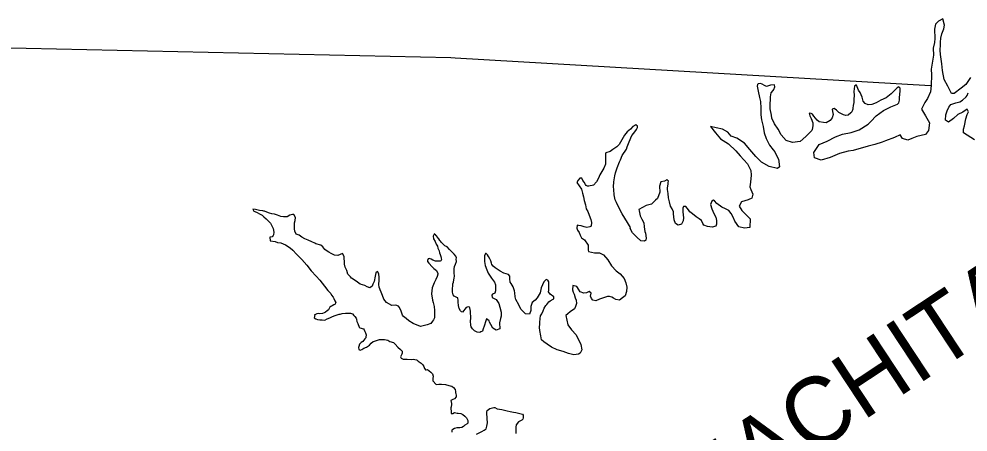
# Model space of a CAD drawing. Extents: x -492261 to -432772, y 1441225 to 1452922.
# Drawn here: x -461436.6 to -461306.2, y 1452192.9 to 1452249.6 of the extents above; entities that cross this region are included whole.
import ezdxf

# ---------------------------------------------------------------- set-up
doc = ezdxf.new("R2010")
doc.units = 0
doc.layers.add('Default', color=7, linetype='Continuous')

msp = doc.modelspace()

# ---------------------------------------------------------------- linework, layer by layer
at = {"layer": 'Default'}
for points in [[(-461305.85, 1452241.57), (-461306.51, 1452240.63), (-461307.13, 1452240.12), (-461308.1, 1452239.36), (-461308.45, 1452239.4), (-461308.96, 1452240.4), (-461309.45, 1452241.32), (-461309.72, 1452242.54), (-461309.8, 1452243.44), (-461309.97, 1452244.74), (-461310.01, 1452245.35), (-461309.99, 1452246.07), (-461309.97, 1452246.45), (-461309.95, 1452246.97), (-461309.78, 1452247.58), (-461309.54, 1452248.26), (-461309.42, 1452248.74), (-461309.66, 1452249.61), (-461310.23, 1452249.33), (-461310.65, 1452248.89), (-461310.82, 1452248.22), (-461310.75, 1452246.91), (-461310.82, 1452246.39), (-461310.99, 1452245.61), (-461310.92, 1452244.63), (-461311.18, 1452243.27), (-461311.25, 1452242.72), (-461311.21, 1452241.95), (-461311.27, 1452240.47), (-461311.33, 1452239.59), (-461311.75, 1452238.71), (-461312.14, 1452238.15), (-461312.58, 1452237.22), (-461312.04, 1452236.3), (-461311.48, 1452235.35), (-461311.64, 1452234.32), (-461312.03, 1452233.77), (-461313.21, 1452233.5), (-461313.93, 1452233.19), (-461314.45, 1452232.98), (-461315.18, 1452233.22), (-461315.51, 1452233.69), (-461316.29, 1452233.36), (-461317.51, 1452232.87), (-461317.98, 1452232.68), (-461318.98, 1452232.37)], [(-461443.96, 1452245.81), (-461377.23, 1452244.31), (-461376.65, 1452244.29), (-461311.37, 1452240.49)], [(-461334.72, 1452240.75), (-461335.02, 1452240.72), (-461335.12, 1452240.6), (-461335.17, 1452240.39), (-461335.03, 1452239.69), (-461334.82, 1452238.82), (-461334.69, 1452238.3), (-461334.65, 1452237.39), (-461334.66, 1452236.47), (-461334.58, 1452235.77), (-461334.32, 1452234.84), (-461334.21, 1452233.99), (-461333.94, 1452233.19), (-461333.46, 1452232.3), (-461332.97, 1452231.65), (-461332.74, 1452231.38), (-461332.51, 1452230.88), (-461332.25, 1452230.36), (-461332.09, 1452229.31), (-461332.36, 1452229.08), (-461333.49, 1452229.34), (-461334.55, 1452229.95), (-461335.36, 1452230.74), (-461336.18, 1452231.69), (-461336.92, 1452232.58), (-461337.95, 1452233.24), (-461338.71, 1452233.51), (-461339.19, 1452234.08), (-461339.9, 1452234.49), (-461340.8, 1452234.65), (-461341.56, 1452234.87), (-461340.87, 1452233.98), (-461340.21, 1452233.18), (-461339.09, 1452232.45), (-461338.11, 1452231.53), (-461337.5, 1452230.84), (-461336.48, 1452229.75), (-461336.04, 1452228.83), (-461335.96, 1452228.18), (-461336.09, 1452227.23), (-461336.16, 1452226.57), (-461336.01, 1452226.2), (-461335.77, 1452225.55), (-461335.89, 1452225), (-461336.41, 1452224.77), (-461337.31, 1452224.53), (-461337.63, 1452223.9), (-461337.27, 1452223.33), (-461336.13, 1452222.17), (-461336.16, 1452221.01), (-461336.91, 1452220.9), (-461337.69, 1452221.09), (-461338.23, 1452221.86), (-461338.44, 1452222.41), (-461338.72, 1452222.91), (-461339.05, 1452223.33), (-461339.53, 1452223.55), (-461340.01, 1452223.77), (-461340.69, 1452224.26), (-461341, 1452224.63), (-461341.15, 1452224.75), (-461341.37, 1452224.62), (-461341.57, 1452224.15), (-461341.38, 1452223.57), (-461341.12, 1452222.92), (-461340.82, 1452222.4), (-461340.73, 1452221.93), (-461340.73, 1452221.45), (-461340.82, 1452221.17), (-461341.32, 1452221.02), (-461341.98, 1452221.11), (-461342.48, 1452221.3), (-461342.63, 1452221.55), (-461342.81, 1452221.95), (-461343.14, 1452222.17), (-461343.55, 1452222.44), (-461344.05, 1452222.88), (-461344.41, 1452223.16), (-461344.61, 1452223.43), (-461344.97, 1452223.85), (-461345.29, 1452223.87), (-461345.39, 1452223.64), (-461345.36, 1452223.12), (-461345.3, 1452222.32), (-461345.32, 1452221.89), (-461345.56, 1452221.44), (-461345.99, 1452221.3), (-461346.37, 1452221.55), (-461346.57, 1452222.05), (-461346.66, 1452222.87), (-461346.66, 1452223.15), (-461346.82, 1452223.57), (-461347.07, 1452223.92), (-461347.21, 1452224.5), (-461347.34, 1452225.07), (-461347.4, 1452225.67), (-461347.48, 1452226.2), (-461347.46, 1452226.37), (-461347.39, 1452226.97), (-461347.39, 1452227.17), (-461347.34, 1452227.35)], [(-461318.98, 1452232.37), (-461319.9, 1452232.13), (-461321.95, 1452231.55), (-461322.67, 1452231.47), (-461323.85, 1452231.15), (-461325.12, 1452230.61), (-461326.36, 1452230.22), (-461327.27, 1452230.53), (-461327.36, 1452231.28), (-461326.64, 1452232.39), (-461325.55, 1452232.83), (-461324.4, 1452233.42), (-461323.43, 1452233.79), (-461322.23, 1452234.03), (-461321.16, 1452234.4), (-461319.89, 1452235.16), (-461319.55, 1452235.54), (-461318.8, 1452236.31), (-461317.81, 1452237.05), (-461316.82, 1452237.54), (-461315.89, 1452237.9), (-461315.7, 1452238.1), (-461315.63, 1452238.48), (-461315.63, 1452238.85), (-461315.52, 1452239.68), (-461315.5, 1452240.11), (-461315.7, 1452240.28), (-461315.95, 1452240.15), (-461316.25, 1452239.85), (-461316.74, 1452239.32), (-461317.46, 1452238.8), (-461318.16, 1452238.47), (-461318.8, 1452238.11), (-461319.4, 1452237.85), (-461319.9, 1452237.82), (-461320.33, 1452237.99), (-461320.58, 1452238.31), (-461320.72, 1452238.86), (-461321.03, 1452239.51), (-461321.26, 1452239.83), (-461321.52, 1452240.53), (-461321.59, 1452240.53), (-461321.79, 1452240.4), (-461321.88, 1452239.67), (-461321.85, 1452239.17), (-461321.87, 1452238.54), (-461321.86, 1452238.34), (-461321.88, 1452238.14), (-461321.95, 1452237.74), (-461322, 1452237.39), (-461322.02, 1452237.24), (-461322.17, 1452236.86), (-461322.29, 1452236.71), (-461322.66, 1452236.43), (-461322.96, 1452236.35), (-461323.32, 1452236.45), (-461323.92, 1452236.76), (-461324.25, 1452237.11), (-461324.6, 1452237.33), (-461324.85, 1452237.25), (-461324.82, 1452236.93), (-461324.72, 1452236.48), (-461324.86, 1452236.02), (-461325.13, 1452235.67), (-461325.66, 1452235.36), (-461326.06, 1452235.38), (-461326.63, 1452235.5), (-461326.94, 1452235.74), (-461327.37, 1452236.29), (-461327.58, 1452236.54), (-461327.75, 1452236.64), (-461328.03, 1452236.68), (-461327.92, 1452236.33), (-461327.72, 1452235.96), (-461327.53, 1452235.36), (-461327.53, 1452234.96), (-461327.6, 1452234.43), (-461327.67, 1452234.31), (-461328.49, 1452233.47), (-461329.23, 1452232.78), (-461330.3, 1452232.64), (-461331.16, 1452232.93), (-461331.87, 1452233.72), (-461332.28, 1452234.49), (-461332.79, 1452235.24), (-461333.15, 1452236.01), (-461333.21, 1452236.39), (-461333.37, 1452237.29), (-461333.38, 1452238.01), (-461333.34, 1452238.51), (-461333.34, 1452238.94), (-461333.25, 1452239.49), (-461332.98, 1452239.8), (-461332.88, 1452239.92), (-461332.71, 1452240.28), (-461332.79, 1452240.58), (-461333.31, 1452240.52), (-461333.89, 1452240.36), (-461334.14, 1452240.46), (-461334.49, 1452240.65), (-461334.72, 1452240.75)], [(-461305.31, 1452233.03), (-461306.8, 1452233.96), (-461306.83, 1452234.49), (-461306.66, 1452234.94), (-461306.5, 1452235.92), (-461306.33, 1452236.48), (-461306.14, 1452236.85), (-461306.32, 1452237.25), (-461306.89, 1452236.84), (-461307.58, 1452236.48), (-461308.2, 1452235.97), (-461308.87, 1452235.44), (-461309.28, 1452235.71), (-461309.24, 1452236.46), (-461309.04, 1452237.01), (-461308.85, 1452237.52), (-461308.55, 1452237.87), (-461307.88, 1452238.11), (-461307.31, 1452238.24), (-461306.96, 1452238.45), (-461306.46, 1452238.93), (-461306.32, 1452239.11), (-461306.17, 1452239.48)], [(-461347.34, 1452227.35), (-461347.55, 1452227.55), (-461347.87, 1452227.37), (-461348.37, 1452227.24), (-461348.56, 1452226.68), (-461348.55, 1452225.83), (-461348.87, 1452224.95), (-461349.14, 1452224.74), (-461349.66, 1452224.21), (-461350.41, 1452224), (-461351.4, 1452223.44), (-461351.37, 1452223.26), (-461351.22, 1452222.61), (-461351.01, 1452222.11), (-461350.73, 1452221.62), (-461350.67, 1452221.07), (-461350.59, 1452220.44), (-461350.51, 1452220.19), (-461350.42, 1452219.54), (-461350.47, 1452219.24), (-461350.64, 1452219.11), (-461351.12, 1452219.16), (-461351.68, 1452219.65), (-461352.29, 1452220.27), (-461352.59, 1452220.84), (-461352.57, 1452220.99), (-461352.98, 1452221.69), (-461353.34, 1452222.28), (-461353.7, 1452222.88), (-461354.11, 1452223.65), (-461354.5, 1452224.4), (-461354.68, 1452224.77), (-461354.78, 1452225.45), (-461354.84, 1452226.2), (-461354.9, 1452226.55), (-461354.86, 1452227.25), (-461354.72, 1452228.08), (-461354.62, 1452228.5), (-461354.38, 1452229.16), (-461354.07, 1452229.99), (-461353.92, 1452230.29), (-461353.68, 1452230.87), (-461353.11, 1452231.73), (-461353.02, 1452232.08), (-461352.75, 1452232.76), (-461352.36, 1452233.62), (-461352.09, 1452233.95), (-461351.72, 1452234.46), (-461351.6, 1452234.71), (-461351.58, 1452234.91), (-461351.83, 1452235.08), (-461352.23, 1452234.83), (-461352.55, 1452234.47), (-461353, 1452234.14), (-461353.39, 1452233.66), (-461353.76, 1452233.03), (-461354.12, 1452232.37), (-461354.45, 1452232.06), (-461354.99, 1452231.71), (-461355.36, 1452231.43), (-461355.94, 1452231.24), (-461355.99, 1452231.09), (-461355.98, 1452230.62), (-461355.97, 1452229.66), (-461356.24, 1452229.11), (-461356.75, 1452228.2), (-461356.94, 1452227.75), (-461357.21, 1452227.27), (-461357.66, 1452226.81), (-461357.83, 1452226.76), (-461358.08, 1452226.7), (-461358.28, 1452226.68), (-461358.48, 1452226.67), (-461358.66, 1452226.75), (-461358.76, 1452226.87), (-461358.94, 1452227.22), (-461359.12, 1452227.44), (-461359.25, 1452227.76), (-461359.5, 1452227.74), (-461359.75, 1452227.48), (-461359.94, 1452227.15), (-461359.61, 1452226.71), (-461359.3, 1452226.24), (-461359.15, 1452225.69), (-461359.01, 1452225.19), (-461358.91, 1452224.69), (-461358.75, 1452224.11), (-461358.64, 1452223.56), (-461358.41, 1452223.19), (-461358.23, 1452222.67), (-461358.02, 1452222.09), (-461357.92, 1452221.69), (-461357.98, 1452221.17), (-461358.16, 1452221.09), (-461358.56, 1452221.01), (-461358.94, 1452221.08), (-461359.34, 1452221.22), (-461359.69, 1452221.27), (-461359.89, 1452221.29), (-461359.94, 1452220.89), (-461359.86, 1452220.62)], [(-461402.5, 1452223.09), (-461402.85, 1452223.22), (-461402.93, 1452223.24), (-461403.05, 1452223.26), (-461403.51, 1452223.33), (-461404.06, 1452223.45), (-461404.44, 1452223.49), (-461404.28, 1452223.25), (-461403.93, 1452223.1), (-461403.42, 1452222.83), (-461403.17, 1452222.66), (-461402.92, 1452222.46), (-461402.59, 1452222.19), (-461402.34, 1452221.92), (-461402.26, 1452221.87), (-461402.01, 1452221.6), (-461401.85, 1452221.32), (-461401.62, 1452220.83), (-461401.54, 1452220.35), (-461401.58, 1452219.97), (-461401.63, 1452219.87), (-461401.8, 1452219.7), (-461402.08, 1452219.64), (-461402.07, 1452219.17), (-461401.35, 1452219.05), (-461401.04, 1452218.95), (-461400.59, 1452218.86), (-461399.96, 1452218.59), (-461399.3, 1452218.18), (-461398.95, 1452217.88), (-461398.42, 1452217.34), (-461397.71, 1452216.59), (-461397.02, 1452215.8), (-461396.41, 1452215.06), (-461395.72, 1452214.32), (-461395.24, 1452213.77), (-461394.58, 1452212.93), (-461394.12, 1452212.36), (-461393.71, 1452211.91), (-461393.61, 1452211.69), (-461393.4, 1452211.42), (-461393.3, 1452211.22), (-461393.17, 1452210.94), (-461393.04, 1452210.69), (-461393.07, 1452210.59), (-461393.14, 1452210.49), (-461393.19, 1452210.44), (-461393.29, 1452210.37), (-461393.54, 1452210.24), (-461393.71, 1452210.16), (-461393.86, 1452210.03), (-461393.96, 1452209.88), (-461394.06, 1452209.68), (-461394.21, 1452209.55), (-461394.45, 1452209.35), (-461394.63, 1452209.27), (-461394.88, 1452209.19), (-461395.25, 1452209.14), (-461395.48, 1452209.16), (-461395.65, 1452209.13), (-461395.9, 1452209), (-461395.9, 1452209.03), (-461395.97, 1452208.83), (-461395.97, 1452208.78), (-461396, 1452208.6), (-461395.77, 1452208.43), (-461395.57, 1452208.38), (-461395.24, 1452208.33), (-461394.97, 1452208.31), (-461394.92, 1452208.31), (-461394.54, 1452208.29), (-461394.24, 1452208.47), (-461393.84, 1452208.6), (-461393.59, 1452208.71), (-461393.24, 1452208.86), (-461393, 1452208.97), (-461392.57, 1452209.07), (-461392.45, 1452209.1), (-461392.17, 1452209.2), (-461391.72, 1452209.23), (-461391.37, 1452209.24), (-461391, 1452209.24), (-461390.74, 1452209.15), (-461390.54, 1452208.92), (-461390.41, 1452208.75), (-461390.26, 1452208.53), (-461390.21, 1452208.4), (-461390.21, 1452208.38), (-461390.15, 1452208.1), (-461390.02, 1452207.83), (-461389.84, 1452207.31), (-461389.72, 1452207.23), (-461389.21, 1452207.06), (-461389.14, 1452206.94), (-461389.03, 1452206.71), (-461388.98, 1452206.52), (-461388.88, 1452206.27), (-461388.88, 1452206.19), (-461388.9, 1452205.99), (-461388.9, 1452205.84), (-461389.04, 1452205.71)], [(-461379.22, 1452215.09), (-461379.04, 1452214.69), (-461379.04, 1452214.57), (-461379.11, 1452214.27), (-461379.31, 1452213.84), (-461379.53, 1452213.41), (-461379.82, 1452212.7), (-461379.88, 1452211.88), (-461379.75, 1452211), (-461379.67, 1452210.7), (-461379.53, 1452210.13), (-461379.5, 1452209.58), (-461379.49, 1452208.97), (-461379.46, 1452208.7), (-461379.49, 1452208.57), (-461379.61, 1452208.32), (-461379.76, 1452208.12), (-461380, 1452207.79), (-461380.5, 1452207.61), (-461381.38, 1452207.39), (-461382.41, 1452207.83), (-461382.99, 1452208.17), (-461383.37, 1452208.5), (-461383.75, 1452208.77), (-461383.88, 1452208.94), (-461384.08, 1452209.51), (-461384.29, 1452209.99), (-461384.42, 1452210.21), (-461384.8, 1452210.31), (-461385.35, 1452210.3), (-461386.08, 1452210.69), (-461386.26, 1452210.91), (-461386.44, 1452211.16), (-461386.64, 1452211.66), (-461386.8, 1452212.11), (-461386.93, 1452212.41), (-461387.01, 1452212.58), (-461387.08, 1452212.78), (-461387.11, 1452213.18), (-461387.12, 1452213.26), (-461387.1, 1452213.66), (-461387.1, 1452214.01), (-461387.1, 1452214.11), (-461387.11, 1452214.61), (-461387.29, 1452214.96), (-461387.54, 1452214.75), (-461387.61, 1452214.33), (-461387.77, 1452213.57), (-461387.94, 1452213.19), (-461388.06, 1452212.94), (-461388.36, 1452212.69), (-461388.71, 1452212.86), (-461389.07, 1452213.03), (-461389.69, 1452213.2), (-461390.05, 1452213.47), (-461390.38, 1452213.71), (-461390.86, 1452214.03), (-461391.04, 1452214.23), (-461391.39, 1452214.6), (-461391.52, 1452215.1), (-461391.75, 1452215.55), (-461391.86, 1452215.97), (-461391.86, 1452216.27), (-461391.87, 1452216.77), (-461391.9, 1452217.02), (-461392.13, 1452217.42), (-461392.78, 1452217.16), (-461393.23, 1452217.18), (-461393.68, 1452217.43), (-461394.01, 1452217.62), (-461394.36, 1452217.82), (-461394.54, 1452217.99), (-461394.67, 1452218.16), (-461394.82, 1452218.34), (-461395.08, 1452218.58), (-461395.76, 1452218.75), (-461395.93, 1452218.85), (-461396.31, 1452219.04), (-461396.81, 1452219.24), (-461397.27, 1452219.43), (-461397.7, 1452219.68), (-461398.08, 1452219.92), (-461398.5, 1452220.09), (-461398.68, 1452220.47), (-461398.71, 1452220.82), (-461398.69, 1452221.19), (-461398.72, 1452221.54), (-461398.7, 1452221.62), (-461398.63, 1452221.94), (-461398.58, 1452222.35), (-461398.79, 1452222.79), (-461398.99, 1452222.77), (-461399.34, 1452222.69), (-461399.71, 1452222.46), (-461400.21, 1452222.45), (-461400.59, 1452222.49), (-461401.04, 1452222.69), (-461401.47, 1452222.83), (-461401.82, 1452222.85), (-461402.15, 1452222.95), (-461402.5, 1452223.09)], [(-461359.86, 1452220.62), (-461359.63, 1452220.29), (-461359.47, 1452219.92), (-461359.29, 1452219.55), (-461358.89, 1452219.28), (-461358.38, 1452218.58), (-461358.35, 1452218.51), (-461358.37, 1452217.88), (-461358.31, 1452217.71), (-461357.51, 1452217.49), (-461356.83, 1452217.52), (-461356.28, 1452217.23), (-461355.69, 1452216.54), (-461355.16, 1452215.74), (-461354.52, 1452215.03), (-461353.97, 1452214.63), (-461353.41, 1452213.99), (-461353.2, 1452213.39), (-461353.06, 1452212.82), (-461353.11, 1452212.21), (-461353.3, 1452211.63), (-461353.67, 1452211.33), (-461354.09, 1452211.02), (-461354.57, 1452211.09), (-461354.87, 1452211.29), (-461355.1, 1452211.43), (-461355.43, 1452211.53), (-461355.73, 1452211.53), (-461356.8, 1452211.14), (-461357.3, 1452210.9), (-461357.75, 1452211), (-461357.93, 1452211.25), (-461358.03, 1452211.57), (-461357.94, 1452211.97), (-461358.22, 1452212.19), (-461358.59, 1452212.04), (-461358.97, 1452211.96), (-461359.49, 1452212.15), (-461359.72, 1452212.5), (-461359.83, 1452212.77), (-461359.93, 1452212.9), (-461360.48, 1452213.02), (-461360.52, 1452212.41), (-461360.42, 1452212.09), (-461360.29, 1452211.84), (-461360.18, 1452211.34), (-461360.03, 1452211.02), (-461359.97, 1452210.57), (-461360.12, 1452210.14), (-461360.27, 1452209.84), (-461360.86, 1452209.4), (-461361.18, 1452209.15), (-461361.43, 1452208.89)], [(-461371.45, 1452207.15), (-461371.76, 1452207.65), (-461371.91, 1452208), (-461371.97, 1452208.17), (-461372.32, 1452208.44), (-461372.42, 1452208.19), (-461372.68, 1452207.44), (-461372.8, 1452207.09), (-461372.9, 1452206.78), (-461373.1, 1452206.68), (-461373.27, 1452206.58), (-461373.63, 1452206.62), (-461373.8, 1452206.7), (-461374, 1452206.82), (-461374.28, 1452207.07), (-461374.44, 1452207.34), (-461374.49, 1452207.56), (-461374.52, 1452208.14), (-461374.48, 1452208.52), (-461374.51, 1452208.84), (-461374.54, 1452209.14), (-461374.54, 1452209.39), (-461374.54, 1452209.52), (-461374.62, 1452209.94), (-461374.65, 1452210.07), (-461374.85, 1452210.11), (-461375.12, 1452209.99), (-461375.64, 1452209.38), (-461375.77, 1452209.4), (-461375.77, 1452209.43), (-461375.92, 1452209.55), (-461376.1, 1452209.87), (-461376.18, 1452210.3), (-461376.23, 1452210.72), (-461376.21, 1452210.97), (-461376.29, 1452211.32), (-461376.42, 1452211.37), (-461376.6, 1452211.47), (-461376.77, 1452211.57), (-461376.92, 1452211.76), (-461377, 1452212.09), (-461377.03, 1452212.26), (-461377.01, 1452212.59), (-461376.97, 1452213.02), (-461376.94, 1452213.27), (-461376.87, 1452213.49), (-461376.83, 1452213.8), (-461376.78, 1452214.05), (-461376.73, 1452214.32), (-461376.76, 1452214.77), (-461376.77, 1452215.15), (-461376.77, 1452215.33), (-461376.75, 1452215.65), (-461376.6, 1452215.95), (-461376.48, 1452216.31), (-461376.49, 1452216.66), (-461376.47, 1452216.83), (-461376.57, 1452217.06), (-461376.8, 1452217.33), (-461377.08, 1452217.63), (-461377.41, 1452217.97), (-461377.76, 1452218.34), (-461378.07, 1452218.49), (-461378.34, 1452218.74), (-461378.55, 1452218.96), (-461378.67, 1452219.11), (-461378.75, 1452219.21), (-461378.9, 1452219.41), (-461378.96, 1452219.53), (-461379.06, 1452219.65), (-461379.21, 1452219.85), (-461379.29, 1452219.9), (-461379.29, 1452219.93), (-461379.54, 1452220.1), (-461379.54, 1452220.07), (-461379.64, 1452219.8), (-461379.63, 1452219.45), (-461379.4, 1452219.05), (-461379.25, 1452218.7), (-461379.09, 1452218.43), (-461379.01, 1452218.15), (-461378.86, 1452217.78), (-461378.8, 1452217.5), (-461378.7, 1452217.3), (-461378.6, 1452217), (-461378.57, 1452216.78), (-461378.52, 1452216.6), (-461378.59, 1452216.43), (-461378.69, 1452216.38), (-461378.99, 1452216.37), (-461379.34, 1452216.37), (-461379.69, 1452216.51), (-461379.95, 1452216.66), (-461380.22, 1452216.71), (-461380.37, 1452216.7), (-461380.44, 1452216.48), (-461380.44, 1452216.3), (-461380.24, 1452216.08), (-461379.78, 1452215.58), (-461379.55, 1452215.36), (-461379.22, 1452215.09)], [(-461361.43, 1452208.89), (-461361.16, 1452207.64), (-461360.65, 1452206.92), (-461360.04, 1452206.26), (-461359.4, 1452204.94), (-461359.26, 1452204.21), (-461359.29, 1452204.09), (-461359.48, 1452203.76), (-461359.71, 1452203.6), (-461360.33, 1452203.5), (-461361.09, 1452203.69), (-461361.82, 1452203.95), (-461362.65, 1452204.19), (-461363.4, 1452204.58), (-461364.01, 1452204.95), (-461364.44, 1452205.29), (-461364.77, 1452205.59), (-461364.88, 1452206.12), (-461365.01, 1452206.87), (-461365.04, 1452207.24), (-461365, 1452207.77), (-461365, 1452207.94), (-461364.98, 1452208.49), (-461364.94, 1452208.87), (-461364.72, 1452209.15), (-461364.55, 1452209.55), (-461364.4, 1452209.93), (-461364.18, 1452210.26), (-461364.03, 1452210.44), (-461363.76, 1452210.77), (-461363.59, 1452210.92), (-461363.19, 1452211.15), (-461363.11, 1452211.2), (-461363.09, 1452211.45), (-461363.6, 1452211.82), (-461363.8, 1452212.14), (-461363.78, 1452212.39), (-461363.76, 1452212.67), (-461363.76, 1452213.07), (-461363.77, 1452213.55), (-461363.9, 1452213.77), (-461364.13, 1452213.87), (-461364.47, 1452213.51), (-461364.81, 1452212.71), (-461364.98, 1452212), (-461365.37, 1452211.35), (-461365.64, 1452211.02), (-461366.06, 1452210.71), (-461366.23, 1452210.13), (-461366.25, 1452209.58), (-461366.42, 1452209.1), (-461366.97, 1452209.12), (-461367.6, 1452209.76), (-461367.91, 1452210.38), (-461368.3, 1452211.11), (-461368.4, 1452211.48), (-461368.46, 1452212.03), (-461368.49, 1452212.31), (-461368.67, 1452212.83), (-461368.95, 1452213.3), (-461369.08, 1452213.5), (-461369.14, 1452213.93), (-461369.14, 1452214.3), (-461369.32, 1452214.52), (-461369.95, 1452214.72), (-461370.48, 1452215.01), (-461370.88, 1452215.25), (-461371.14, 1452215.45), (-461371.42, 1452215.7), (-461371.59, 1452215.9), (-461371.65, 1452216.07), (-461371.75, 1452216.4), (-461371.9, 1452216.67), (-461372.06, 1452216.99), (-461372.19, 1452217.22), (-461372.37, 1452217.44), (-461372.47, 1452217.44), (-461372.59, 1452217.09), (-461372.6, 1452216.33), (-461372.52, 1452215.78), (-461372.31, 1452215.19), (-461372.1, 1452214.74), (-461371.67, 1452214.04), (-461371.26, 1452213.5), (-461371.11, 1452213.1), (-461371.08, 1452212.75), (-461371.09, 1452212.3), (-461371.17, 1452211.99), (-461371.49, 1452211.84), (-461371.59, 1452211.71), (-461371.56, 1452211.36), (-461371.03, 1452211.09), (-461370.65, 1452210.57), (-461370.49, 1452210.05), (-461370.33, 1452209.35), (-461370.3, 1452208.82), (-461370.42, 1452208.5), (-461370.56, 1452207.89), (-461370.52, 1452207.09), (-461371.02, 1452206.91), (-461371.45, 1452207.15)], [(-461389.04, 1452205.71), (-461389.34, 1452205.36), (-461389.56, 1452205.18), (-461389.76, 1452204.98), (-461389.88, 1452204.67), (-461389.91, 1452204.52), (-461389.88, 1452204.22), (-461389.7, 1452204.15), (-461389.45, 1452204.25), (-461389.18, 1452204.41), (-461388.8, 1452204.54), (-461388.41, 1452204.84), (-461388.16, 1452205.12), (-461387.91, 1452205.33), (-461387.74, 1452205.4), (-461387.04, 1452205.61), (-461386.84, 1452205.62), (-461386.69, 1452205.62), (-461386.34, 1452205.6), (-461385.91, 1452205.5), (-461385.61, 1452205.36), (-461385.13, 1452205.19), (-461384.9, 1452204.99), (-461384.5, 1452204.57), (-461384.17, 1452204.23), (-461383.91, 1452204), (-461383.91, 1452203.88), (-461383.93, 1452203.73), (-461383.98, 1452203.6), (-461384.03, 1452203.53), (-461384.13, 1452203.25), (-461384.07, 1452203.05), (-461383.77, 1452202.93), (-461383.22, 1452202.91), (-461382.69, 1452202.89), (-461382.42, 1452202.9), (-461381.97, 1452202.83), (-461381.84, 1452202.78), (-461381.74, 1452202.63), (-461381.44, 1452202.46), (-461381.33, 1452202.38), (-461381.08, 1452202.14), (-461380.95, 1452201.89), (-461380.85, 1452201.64), (-461380.8, 1452201.59), (-461380.72, 1452201.47), (-461380.62, 1452201.47), (-461380.45, 1452201.49), (-461379.97, 1452201.12), (-461379.74, 1452200.9), (-461379.68, 1452200.6), (-461379.68, 1452200.58), (-461379.7, 1452200.28), (-461379.72, 1452199.95), (-461379.27, 1452199.43), (-461378.87, 1452199.46), (-461378.54, 1452199.49), (-461377.96, 1452199.42), (-461377.84, 1452199.37), (-461377.31, 1452199.26), (-461377.11, 1452199.21), (-461376.86, 1452199.04), (-461376.63, 1452198.74), (-461376.6, 1452198.46), (-461376.6, 1452198.31), (-461376.57, 1452198.19), (-461376.49, 1452197.91), (-461376.51, 1452197.74), (-461376.71, 1452197.49), (-461376.98, 1452197.36), (-461377.06, 1452197.33), (-461377.23, 1452197.25), (-461377.21, 1452197.03), (-461377.15, 1452196.9), (-461377.13, 1452196.7), (-461377.2, 1452196.35), (-461377.22, 1452196.23), (-461377.21, 1452195.62), (-461377.19, 1452195.47), (-461377.14, 1452195.45), (-461376.96, 1452195.45), (-461376.71, 1452195.58), (-461376.38, 1452195.51), (-461376.23, 1452195.51), (-461375.86, 1452195.47), (-461375.58, 1452195.3), (-461375.33, 1452195.07), (-461375.12, 1452194.9), (-461375.07, 1452194.88), (-461374.92, 1452194.48), (-461374.89, 1452194.23), (-461374.91, 1452194.15), (-461374.99, 1452194.05), (-461375.31, 1452193.87), (-461375.51, 1452193.69), (-461375.73, 1452193.52), (-461375.98, 1452193.49), (-461376.41, 1452193.48), (-461376.71, 1452193.4), (-461376.98, 1452193.27), (-461377.08, 1452193.15)], [(-461373.72, 1452192.62), (-461372.97, 1452192.98), (-461372.67, 1452193.16), (-461372.4, 1452193.33), (-461372.3, 1452193.71), (-461372.21, 1452194.16), (-461372.24, 1452194.77), (-461372.24, 1452194.87), (-461372.3, 1452195.44), (-461372.3, 1452195.67), (-461372.23, 1452195.87), (-461372.08, 1452196), (-461371.86, 1452196.12), (-461371.33, 1452196.28), (-461371.21, 1452196.26), (-461370.86, 1452196.11), (-461370.23, 1452196), (-461370.03, 1452195.95), (-461369.5, 1452195.83), (-461369.07, 1452195.71), (-461368.64, 1452195.62), (-461368.32, 1452195.6), (-461367.94, 1452195.52), (-461367.41, 1452195.36), (-461367.29, 1452195.21), (-461367.31, 1452194.86), (-461367.35, 1452194.68), (-461367.5, 1452194.55), (-461367.95, 1452194.32), (-461368.25, 1452193.89), (-461368.29, 1452193.59), (-461368.31, 1452193.14), (-461368.31, 1452192.69)], [(-461377.08, 1452193.15), (-461377.1, 1452193.02), (-461377.1, 1452192.87)]]:
    msp.add_lwpolyline(points, dxfattribs=at)

# ---------------------------------------------------------------- texts
msp.add_text('OUACHITA', height=9.24, rotation=33.4445, dxfattribs=at).set_placement((-461350.48, 1452174.68))

doc.saveas('drawing.dxf')
